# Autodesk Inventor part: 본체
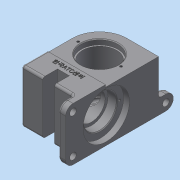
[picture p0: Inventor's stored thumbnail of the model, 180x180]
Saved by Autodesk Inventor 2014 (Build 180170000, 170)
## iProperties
Created: 2023-09
Part Number: 본체
Material: 일반
Document SubType Name: Modeling
Designer: dg
Density: 1 g/cm^3
Appearance: 기본값
Author: dg
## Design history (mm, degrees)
sketch "스케치1"
  geometry: L1 (43, 71)-(43, -35); L2 (43, -35)-(-37, -35); L3 (-37, -35)-(-37, 34); L4 (0, 71)-(43, 71); A1 r 37 centre (0, 34) between (0, 71) and (-37, 34); 1 further point
  constraints: 8 end point, 2 perpendicular, 2 point on circle, 1 centre point, 1 parallel, 1 tangent, 1 vertical, 1 vertical alignment
  dimensions: "d0" = 106 distance between parallel lines of L2 L4; "d2" = 80 distance between parallel lines of L3 L1; "d37" = 37 radius of A1; "d39" = 35 distance from line of point (0, 0) L2; "d40" = 34 distance of point (0, 0) A1.centre
extrude "돌출1" new body sketch "스케치1" stored distance "d5" = 72; taper "d6" = 0 deg
sketch "스케치2"
  geometry: L1 (72, 106)-(72, 0) reference; L2 (0, 0)-(72, 0); L3 (72, 0)-(72, -20); L4 (72, -20)-(0, -20); L5 (0, -20)-(0, 0); 3 further points
  constraints: 8 end point, 2 midpoint, 2 parallel, 1 horizontal, 1 perpendicular, 1 vertical alignment
  dimensions: "d7" = 20 distance of L4.end L2.start
extrude "돌출2" join sketch "스케치2" distance "d8" = 10; taper "d9" = 0 deg
sketch "스케치3"
  geometry: 1 further point
hole "구멍1" sketch "스케치3" at (-36, 35) diameter "d10" = 45; stored, may be unused: countersink angle "d14" = 90 deg, drill point angle "d16" = 0 deg; dims "d11" = 6, "d12" = 63, "d13" = 3, "d15" = 15
sketch "스케치4"
  geometry: 1 further point
hole "구멍2" sketch "스케치4" at (36, -71) diameter "d17" = 45; stored, may be unused: countersink angle "d21" = 90 deg, drill point angle "d23" = 0 deg; dims "d18" = 6, "d19" = 63, "d20" = 8, "d22" = 20
sketch "스케치5"
  geometry: C1 r 22.5 at (0, 0) reference
hole "구멍3" sketch "스케치5" at (0, 0) diameter "d24" = 37; stored, may be unused: countersink angle "d28" = 90 deg, drill point angle "d30" = 0 deg; dims "d25" = 6, "d26" = 63, "d27" = 8, "d29" = 20
node "작업 평면1"
sketch "스케치6"
  geometry: L1 (-37, 0)-(33, 0) reference; L2 (-37, 4.5)-(-37, 67.5) reference; L3 (-37, 0)-(-37, 72) reference; L4 (43, 0)-(33, 0) reference; L5 (43, 0)-(43, 72) reference; L6 (43, 0)-(-37, 0); L7 (-37, 0)-(-37, 3); L8 (-37, 3)-(43, 3); L9 (43, 3)-(43, 0); 1 further point
  constraints: 8 end point, 2 parallel, 1 horizontal, 1 perpendicular, 1 point on line
  dimensions: "d32" = 3 distance of L8.end L4.start
extrude "돌출3" cut sketch "스케치6" distance "d33" = 72; taper "d34" = 0 deg
sketch "스케치7"
  geometry: A1 r 37 centre (37, 35) between (37, 72) and (0, 35) reference; 1 further point
hole "구멍4" sketch "스케치7" at (37, 35) diameter "d41" = 46; stored, may be unused: countersink angle "d45" = 90 deg, drill point angle "d47" = 0 deg; dims "d42" = 6, "d43" = 50, "d44" = 7, "d46" = 47
sketch "스케치8"
  geometry: A1 r 23 centre (0, 0) between (7.007, -21.907) and (-7.007, -21.907) reference; 1 further point
hole "구멍5" sketch "스케치8" at (0, 0) diameter "d48" = 31; stored, may be unused: countersink angle "d52" = 90 deg, drill point angle "d54" = 0 deg; dims "d49" = 6, "d50" = 35, "d51" = 15, "d53" = 19
sketch "스케치9"
  geometry: L1 (0, 0)-(72, 0) reference; L2 (72, 126)-(3, 126) reference; L3 (52, 126)-(52, 136); L4 (72, 136)-(72, 126); A1 r 10 centre (62, 136) between (72, 136) and (52, 136); 1 further point
  constraints: 4 end point, 3 point on circle, 2 tangent, 1 centre point, 1 parallel, 1 perpendicular, 1 point on line
  dimensions: "d55" = 20 distance between parallel lines of L4 L3; "d56" = 136 distance from line of L1 A1.centre
extrude "돌출4" join sketch "스케치9" distance "d57" = 10; taper "d58" = 0 deg
sketch "스케치10"
  geometry: A1 r 10 centre (-62, 136) between (-52, 136) and (-72, 136) reference; 1 further point
hole "구멍6" sketch "스케치10" at (-62, 136) diameter "d59" = 9; stored, may be unused: countersink angle "d63" = 90 deg, drill point angle "d65" = 0 deg; dims "d60" = 6, "d61" = 35, "d62" = 15, "d64" = 19
fillet "모깎기1" dims "d66" = 10
sketch "스케치11"
  geometry: A1 r 10 centre (-10, -10) between (-10, -20) and (0, -10) reference; A2 r 10 centre (-62, -10) between (-72, -10) and (-62, -20) reference; 1 further point
hole "구멍7" sketch "스케치11" at (-62, -10), (-10, -10) diameter "d67" = 9; stored, may be unused: countersink angle "d71" = 90 deg, drill point angle "d73" = 0 deg; dims "d68" = 6, "d69" = 35, "d70" = 15, "d72" = 19
fillet "모깎기2" dims "d74" = 3
fillet "모깎기3" dims "d75" = 0.3
fillet "모깎기4" dims "d76" = 3
fillet "모깎기5" dims "d77" = 3
fillet "모깎기8" dims "d80" = 3
fillet "모깎기9" dims "d81" = 3
fillet "모깎기10" dims "d82" = 3
sketch "스케치12"
  geometry: L1 (-34, -35)-(30, -35) reference; 2 further points
  constraints: 1 vertical alignment, 1 other
  dimensions: "d83" = 27 distance from line of point (0, -8) L1
feature "엠보싱1" sketch "스케치12" dims "d0" = 106, "d2" = 80, "d15" = 15, "d37" = 37, "d39" = 35, "d40" = 34, "d84" = 0.5, "d85" = 0
sketch "스케치13"
  geometry: L1 (-8, -15)-(8, -15); L2 (8, -15)-(8, -35); L3 (8, -35)-(-8, -35); L4 (-8, -35)-(-8, -15); L5 (-34, -35)-(30, -35) reference; 4 further points
  constraints: 8 end point, 3 midpoint, 2 parallel, 1 horizontal, 1 horizontal alignment, 1 perpendicular, 1 vertical alignment
  dimensions: "d86" = 16 distance of L2.end L3.end; "d87" = 20 distance between parallel lines of L5 L1
extrude "돌출5" cut sketch "스케치13" stored distance "d88" = 10; taper "d89" = 0 deg
sketch "스케치14"
  geometry: C1 r 31.5 at (0, 0) reference; 2 further points
  constraints: 2 vertical alignment
  dimensions: "d93" = 26 distance of point (0, 26) C1.centre; "d94" = 52 distance of point (0, -26) point (0, 26)
hole "구멍8" sketch "스케치14" at (0, 26), (0, -26) diameter "d95" = 3.242; stored, may be unused: countersink angle "d99" = 90 deg, drill point angle "d101" = 118 deg; dims "d96" = 8, "d97" = 35, "d98" = 15, "d100" = 10
sketch "스케치15"
  geometry: C1 r 31.5 at (0, 0) reference; 2 further points
  constraints: 2 vertical alignment
  dimensions: "d102" = 26 distance of C1.centre point (0, 26); "d103" = 52 distance of point (0, -26) point (0, 26)
hole "구멍9" sketch "스케치15" at (0, 26), (0, -26) diameter "d104" = 3.242; stored, may be unused: countersink angle "d108" = 90 deg, drill point angle "d110" = 118 deg; dims "d105" = 8, "d106" = 35, "d107" = 15, "d109" = 10
sketch "스케치16"
  geometry: C1 r 25 at (0, -37) reference; 3 further points
  constraints: 2 horizontal alignment
  dimensions: "d111" = 58 distance of point (29, -37) point (-29, -37); "d112" = 29 distance of point (29, -37) C1.centre
hole "구멍10" sketch "스케치16" at (-29, -37), (29, -37) diameter "d113" = 3.242; stored, may be unused: countersink angle "d117" = 90 deg, drill point angle "d119" = 118 deg; dims "d114" = 8, "d115" = 35, "d116" = 15, "d118" = 10
chamfer "모따기2" distance "d120" = 1; stored, may be unused: second distance "d121" = 2, angle "d122" = 45 deg
chamfer "모따기3" distance "d123" = 1; stored, may be unused: second distance "d124" = 2, angle "d125" = 45 deg
chamfer "모따기4" distance "d126" = 1; stored, may be unused: second distance "d127" = 2, angle "d128" = 45 deg
sketch "스케치17"
  geometry: 3 further points
  constraints: 2 vertical alignment
  dimensions: "d129" = 25 distance of point (8, -36) point (8, -11); "d130" = 50 distance of point (8, -61) point (8, -11)
hole "구멍11" sketch "스케치17" at (8, -11), (8, -61) diameter "d131" = 3.242; stored, may be unused: countersink angle "d135" = 90 deg, drill point angle "d137" = 118 deg; dims "d132" = 8, "d133" = 35, "d134" = 15, "d136" = 10
node "솔리드1"
other parameters: "d31" = -72
